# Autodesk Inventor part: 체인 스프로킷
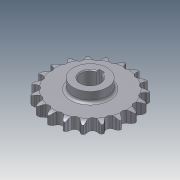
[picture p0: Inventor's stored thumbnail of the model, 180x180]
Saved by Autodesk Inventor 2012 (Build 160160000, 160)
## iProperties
Created: 2013-01
Part Number: 체인 스프로킷
Material: 강
Document SubType Name: Modeling
Designer: KYOUNG IL JANG
Density: 1 g/cm^3
CustomPartVersion: 1
Company: 한국ATC센터
Author: KYOUNG IL JANG
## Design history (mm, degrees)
sketch "이론적 톱니 프로파일"
  geometry: L1 (0, 0)-(0, 45.567); L2 (0, 0)-(14.795, 43.098); L3 (0, 45.567)-(14.795, 43.098); L4 (0, 45.567)-(5.661, 50.015); L5 (5.661, 50.015)-(-5.141, 45.406); L6 (-12.428, 43.493)-(-5.573, 46.417); L7 (-5.141, 45.406)-(-5.573, 46.417); L8 (5.573, 46.417)-(5.141, 45.406); L9 (0, 0)-(8.138, 48.771); A1 r 45.567 centre (0, 0) between (0, 45.567) and (14.795, 43.098); A2 r 49.445 centre (0, 0) between (7.302, 48.903) and (-7.302, 48.903); A3 r 4.545 centre (0, 45.567) between (-3.574, 42.758) and (3.574, 42.758); A4 r 7.453 centre (12.428, 43.493) between (7.302, 48.903) and (5.573, 46.417); A5 r 7.453 centre (-12.428, 43.493) between (-5.573, 46.417) and (-7.302, 48.903); A6 r 11.745 centre (5.661, 50.015) between (-5.141, 45.406) and (-3.574, 42.758); A7 r 11.745 centre (-5.661, 50.015) between (3.574, 42.758) and (5.141, 45.406); 2 further points
  constraints: 18 end point, 15 point on circle, 7 centre point, 3 coincident, 3 point on line, 3 symmetric about line, 3 tangent, 1 equal radius, 1 midpoint, 1 parallel, 1 vertical, 1 other
  dimensions: "d0" = 91.13301 diameter of A1 (computed from da_p, da_z); "d2" = 18.9474 deg angle of L2 L1 (computed from da_z); "d3" = 4.545 radius of A3 (= 0.5 x da_Dr + da_SC); "d10" = 128.158 deg angle of L4 L1 (computed from da_z); "d11" = 15.0526 deg angle of L5 L4 (computed from da_z); "d12" = 7.2 distance of L3.start L4.end (= 0.8 x da_Dr); "d13" = 11.745 distance of L4.end L5.end (= 1.3 x da_Dr + da_SC); "d14" = 12.6 distance of A4.centre L1.end (= 1.4 x da_Dr); "d23" = 4.5 distance from line of L9.end L3 (= da_Ha)
sketch "톱니 프로파일"
  geometry: L1 (0, 0)-(0, 45.567); L2 (0, 45.567)-(4.203, 43.837); L3 (0, 45.567)-(-4.203, 43.837); A1 r 4.545 centre (0, 45.567) between (-4.203, 43.837) and (4.203, 43.837); A2 r 22.68 centre (25.176, 35.206) between (7.12, 48.93) and (4.203, 43.837); A3 r 22.68 centre (-25.176, 35.206) between (-4.203, 43.837) and (-7.12, 48.93); A4 r 49.445 centre (0, 0) between (-7.12, 48.93) and (7.12, 48.93) reference; 1 further point
  constraints: 9 point on circle, 6 end point, 3 centre point, 2 tangent, 1 coincident, 1 equal radius, 1 vertical, 1 other
  dimensions: "d44" = 135.263 deg angle of L3 L2 (= da_Alfa); "d45" = 22.68 radius of A2 (= da_Re); "d46" = 4.545 radius of A1 (= da_Ri)
sketch "단면 프로파일"
  geometry: L1 (49.445, 0)-(-49.445, 0) reference; L2 (33.265, 6.65)-(-33.265, 6.65); L3 (-33.265, 6.65)-(-33.265, -6.65); L4 (-33.265, -6.65)-(33.265, -6.65); L5 (33.265, -6.65)-(33.265, 6.65); L6 (33.265, 6.65)-(49.445, 6.65); L7 (49.445, 6.65)-(49.445, -6.65); L8 (49.445, -6.65)-(33.265, -6.65); L9 (33.265, -6.65)-(33.265, 6.65); L10 (42.183, 6.65)-(0, 6.65); L11 (0, 6.65)-(0, -6.65); L12 (0, -6.65)-(42.183, -6.65); L13 (0, 6.65)-(0, -6.65); L14 (49.445, 4.775)-(49.445, -4.775); A1 r 15 centre (42.183, -8.35) between (49.445, 4.775) and (42.183, 6.65); A2 r 15 centre (42.183, 8.35) between (42.183, -6.65) and (49.445, -4.775); 2 further points
  constraints: 26 end point, 7 midpoint, 5 perpendicular, 4 parallel, 4 point on circle, 3 point on line, 3 symmetric about line, 2 centre point, 2 horizontal, 2 tangent, 1 collinear, 1 other
  dimensions: "d30" = 13.3 distance between parallel lines of L8 L6 (= da_Bf); "d31" = 66.53007 distance between parallel lines of L3 L5 (= da_Ds); "d32" = 13.3 distance between parallel lines of L4 L2 (= da_Bs); "d33" = 1.875 distance from line of L14.start L6 (= da_Ba); "d34" = 15 radius of A1 (= da_Rx); "d43" = 6.65 distance between parallel lines of L4 L1 (computed from da_k, da_pt, da_Bs)
revolve "슈라우드" stored, may be unused: angle "d36" = 90 deg
revolve "스트랜드" stored, may be unused: angle "d37" = 90 deg
extrude "이론적 톱니" cut sketch "이론적 톱니 프로파일" stored distance "d18" = 10; taper "d19" = 0 deg; dims "d49" = 0, "form_type" = 0 [user parameter]
extrude "톱니" cut sketch "톱니 프로파일" stored distance "d47" = 10; taper "d48" = 0 deg; dims "d50" = 10, "form_type" = 0 [user parameter]
node "타이밍 평면"
node "작업 평면3"
sketch "스케치5"
  geometry: C1 r 20 at (0, -45.567); 1 further point
  constraints: 1 centre point, 1 coincident
  dimensions: "d52" = 40 diameter of C1
extrude "돌출4" join sketch "스케치5" stored distance "d53" = 10; taper "d54" = 0 deg
sketch "스케치6"
  geometry: L1 (3, 10.583)-(3, 13.8); L2 (3, 13.8)-(-3, 13.8); L3 (-3, 13.8)-(-3, 10.583); A1 r 11 centre (0, 0) between (3, 10.583) and (-3, 10.583); 1 further point
  constraints: 6 end point, 2 parallel, 2 point on circle, 1 centre point, 1 coincident, 1 perpendicular, 1 vertical
  dimensions: "d55" = 22 diameter of A1; "d56" = 24.8 dimension on A1 L2 (computed from d55); "d57" = 6 distance of L1.end L2.end
extrude "돌출5" cut sketch "스케치6" stored distance "d58" = 10; taper "d59" = 0 deg
fillet "모깎기2" dims "d60" = 3
chamfer "모따기1" distance "d61" = 1; stored, may be unused: second distance "d62" = 2, angle "d63" = 45 deg
body "Solid1"
pattern_linear "스트랜드 패턴" dims "d40" = 24 (= da_pt)
pattern_circular "톱니 패턴" dims angle "d21" = 360 deg
other parameters: "da_p" = 15 [user parameter; used in 1 equation term], "da_Dr" = 9 [user parameter; used in 4 equation terms], "da_SC" = 0.045 [user parameter; used in 2 equation terms], "da_Ha" = 4.5 [user parameter; used in 1 equation term], "da_pt" = 24 [user parameter; used in 2 equation terms], "da_Bf" = 13.3 [user parameter; used in 1 equation term], "d28" = 0, "d29" = 0, "da_Ba" = 1.875 [user parameter; used in 1 equation term], "da_Rx" = 15 [user parameter; used in 1 equation term], "da_Ra" = 0.6 [user parameter], "da_Bs" = 13.3 [user parameter; used in 2 equation terms], "da_Ds" = 66.53007 [user parameter; used in 1 equation term], "d42" = 0, "da_Re" = 22.68 [user parameter; used in 1 equation term], "da_Ri" = 4.545 [user parameter; used in 1 equation term], "da_Alfa" = 135.263 deg [user parameter; used in 1 equation term], "d51" = -25
